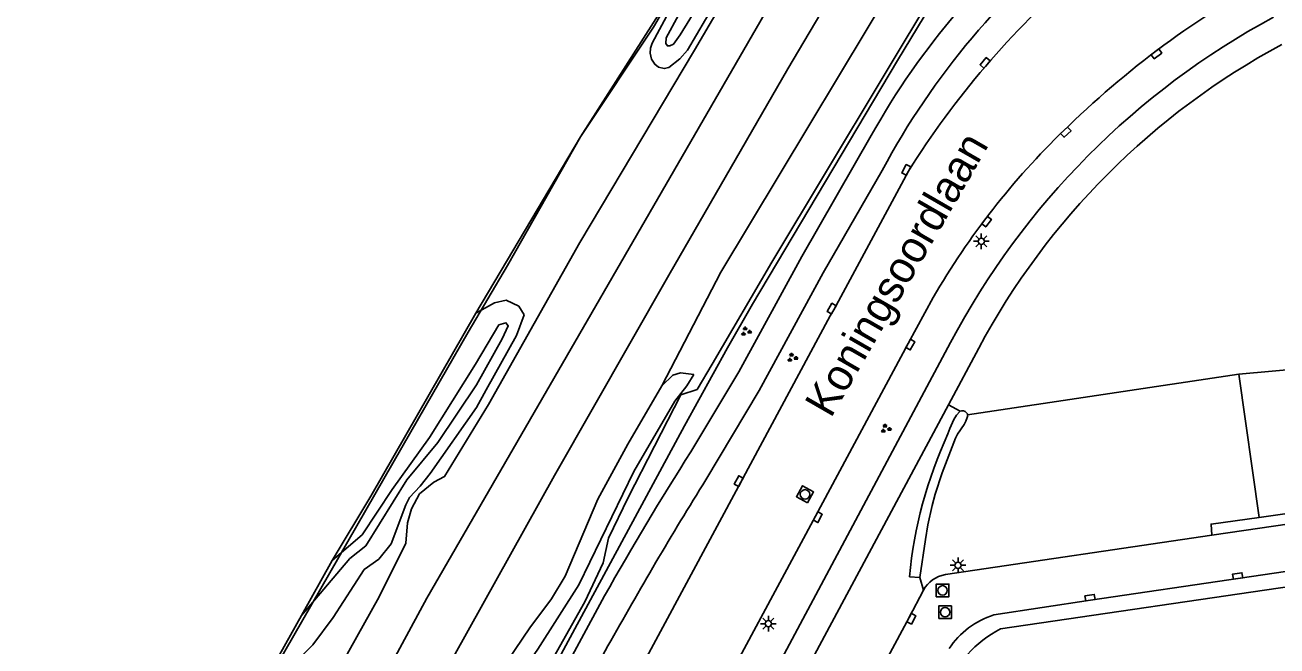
# Model space of a CAD drawing. Extents: x 136000 to 141000, y 400494 to 402006.
# Drawn here: x 137725.4 to 137824.5, y 400640.9 to 400690.1 of the extents above; entities that cross this region are included whole.
import ezdxf

# ---------------------------------------------------------------- set-up
doc = ezdxf.new("R2010")
doc.units = 0
for name, color, linetype in [('gg-afsc-hekwerk', 7, 'Continuous'), ('gg-anno-openbare ruimte label', 7, 'Continuous'), ('gg-aspt-spoorlijn', 7, 'Continuous'), ('gg-knt-BGT kruinlijn', 7, 'Continuous'), ('gg-knt-verharding', 7, 'Continuous'), ('gg-knt-verharding nz', 7, 'Continuous'), ('gt-grn-groengrens', 7, 'Continuous'), ('gt-grn-vlakafsluiter', 7, 'Continuous'), ('gt-symb-groenvak', 7, 'Continuous'), ('gt-symb-kolk', 7, 'Continuous'), ('gt-symb-lichtmast', 7, 'Continuous'), ('gt-symb-rioolschacht', 7, 'Continuous'), ('gx-grn-maaiveld', 7, 'Continuous')]:
    doc.layers.add(name, color=color, linetype=linetype)

# ---------------------------------------------------------------- blocks, each defined once
blk = doc.blocks.new('gt0-KOLK')
at = {"layer": 'gt-symb-kolk'}
blk.add_lwpolyline([(0, 0), (0.375, 0), (0.375, 0.4), (-0.375, 0.4), (-0.375, 0), (0, 0)], dxfattribs=at)
blk = doc.blocks.new('gt0-GRVAK')
at = {"layer": 'gt-symb-groenvak'}
for p, q in [((-0.11, 0.189), (-0.228, 0.24)), ((-0.182, 0.153), (0.088, 0.153)), ((-0.091, 0.211), (-0.156, 0.322)), ((-0.047, 0.214), (-0.047, 0.393)), ((-0.004, 0.211), (0.061, 0.322)), ((0.015, 0.189), (0.133, 0.24)), ((0.262, -0.052), (0.197, 0.059)), ((0.305, -0.049), (0.305, 0.13)), ((0.349, -0.052), (0.414, 0.059)), ((-0.245, -0.228), (-0.363, -0.177)), ((-0.318, -0.264), (-0.047, -0.264)), ((-0.226, -0.206), (-0.291, -0.095)), ((-0.183, -0.203), (-0.183, -0.024)), ((-0.139, -0.206), (-0.074, -0.095)), ((-0.12, -0.228), (-0.002, -0.177)), ((0.243, -0.074), (0.125, -0.023)), ((0.17, -0.11), (0.441, -0.11)), ((0.368, -0.074), (0.486, -0.023))]:
    blk.add_line(p, q, dxfattribs=at)
blk = doc.blocks.new('gt0-LMAST')
at = {"layer": 'gt-symb-lichtmast'}
for p, q in [((-0.182, 0.173), (-0.447, 0.438)), ((-0.005, 0.246), (-0.005, 0.621)), ((0.172, 0.173), (0.437, 0.438)), ((-0.255, -0.004), (-0.63, -0.004)), ((-0.182, -0.181), (-0.447, -0.446)), ((-0.005, -0.254), (-0.005, -0.629)), ((0.437, -0.446), (0.172, -0.181)), ((0.245, -0.004), (0.62, -0.004))]:
    blk.add_line(p, q, dxfattribs=at)
blk.add_circle((-0.005, -0.004), 0.25, dxfattribs=at)
blk = doc.blocks.new('gt0-RS')
at = {"layer": 'gt-symb-rioolschacht'}
blk.add_lwpolyline([(-0.5, -0.5), (0.5, -0.5), (0.5, 0.5), (-0.5, 0.5)], close=True, dxfattribs=at)
blk.add_circle((0, 0), 0.375, dxfattribs=at)

msp = doc.modelspace()

# ---------------------------------------------------------------- linework, layer by layer
at = {"layer": 'gg-afsc-hekwerk'}
for points in [[(137764.981, 400635.036), (137777.587, 400658.382), (137780.977, 400664.557), (137782.964, 400668.027), (137794.433, 400687.317), (137802.189, 400700.171)], [(137673.08, 400500), (137679.073, 400510.921), (137690.13, 400531.89), (137697.24, 400544.984), (137704.068, 400557.915), (137707.189, 400563.436), (137711.427, 400571.311), (137716.123, 400579.98), (137726.152, 400597.957), (137729.988, 400605.237), (137728.496, 400607.87), (137729.573, 400610.191), (137736.665, 400624.377), (137755.903, 400657.896), (137760.436, 400665.803), (137763.569, 400671.08), (137769.351, 400681.269), (137775.737, 400691.291)]]:
    msp.add_lwpolyline(points, dxfattribs=at)
at = {"layer": 'gg-aspt-spoorlijn'}
for points in [[(137684.39, 400500), (137744.114, 400612.492), (137758.139, 400637.988), (137767.293, 400654.443), (137776.333, 400670.325), (137785.754, 400686.663), (137800.006, 400710.764), (137824.915, 400751.953), (137852.49, 400796.886), (137902.562, 400879.015), (137911.759, 400893.922), (138126.55, 401245.58)], [(137679.974, 400500), (137705.761, 400548.658), (137729.975, 400594.291), (137757.164, 400644.72), (137784.911, 400692.764), (137800.887, 400719.606), (137819.846, 400750.938), (138062.157, 401147.541)]]:
    msp.add_lwpolyline(points, dxfattribs=at)
at = {"layer": 'gg-knt-BGT kruinlijn'}
for p, q in [((137761.053, 400667.307), (137762.541, 400668.13)), ((137762.541, 400668.13), (137763.455, 400668.336)), ((137763.455, 400668.336), (137764.472, 400667.851)), ((137752.736, 400652.807), (137761.053, 400667.307)), ((137764.882, 400667.161), (137764.271, 400665.545)), ((137764.472, 400667.851), (137764.882, 400667.161)), ((137764.271, 400665.545), (137761.886, 400661.232)), ((137775.776, 400661.546), (137776.662, 400662.38)), ((137777.258, 400662.587), (137776.662, 400662.38)), ((137778.308, 400662.447), (137777.258, 400662.587)), ((137761.886, 400661.232), (137761.103, 400659.816)), ((137761.103, 400659.816), (137757.43, 400654.587)), ((137757.43, 400654.587), (137756.636, 400653.582)), ((137756.636, 400653.582), (137755.796, 400652.695)), ((137749.695, 400647.703), (137752.736, 400652.807)), ((137755.796, 400652.695), (137755.508, 400652.104)), ((137755.508, 400652.104), (137754.362, 400649.033)), ((137754.362, 400649.033), (137753.379, 400647.808)), ((137753.379, 400647.808), (137752.22, 400646.991)), ((137752.22, 400646.991), (137749.761, 400643.188)), ((137749.761, 400643.188), (137748.139, 400641.005)), ((137748.139, 400641.005), (137745.974, 400638.819))]:
    msp.add_line(p, q, dxfattribs=at)
at = {"layer": 'gg-knt-verharding'}
for p, q in [((137807.982, 400682.131), (137807.627, 400681.801)), ((137798.464, 400660.045), (137800.866, 400664.535)), ((137802.6, 400642.275), (137911.341, 400658.226)), ((137829.009, 400651.137), (137819.324, 400649.706)), ((137819.324, 400649.706), (137798.225, 400646.58))]:
    msp.add_line(p, q, dxfattribs=at)
for points in [[(137792.362, 400681.374), (137786.87, 400671.804), (137781.869, 400662.645), (137778.081, 400656.319)], [(137734.501, 400565.046), (137735.753, 400567.466), (137743.507, 400582.034), (137759.087, 400611.164), (137766.889, 400625.715), (137782.046, 400653.901), (137789.115, 400667.087), (137789.397, 400667.561), (137795.307, 400678.565)], [(137793.23, 400678.613), (137788.563, 400670.492), (137783.49, 400661.185), (137779.265, 400654.107)], [(137797.261, 400668.546), (137795.276, 400664.906), (137787.956, 400651.225), (137780.617, 400637.565), (137775.49, 400627.953)], [(137753.626, 400580.954), (137765.363, 400602.667), (137785.888, 400641.077), (137798.639, 400664.975)], [(137754.898, 400578.717), (137767.638, 400602.418), (137798.464, 400660.045)], [(137796.483, 400645.347), (137795.357, 400643.183), (137793.681, 400640.037)], [(137771.245, 400644.9), (137757.197, 400618.818), (137729.365, 400566.677), (137726.956, 400562.179)], [(137771.514, 400640.926), (137759.873, 400619.176), (137745.495, 400592.359), (137731.641, 400566.467)]]:
    msp.add_lwpolyline(points, dxfattribs=at)
for centre, radius, start, end in [((137842.746, 400653.567), 57.547, 127.20922, 151.10568), ((137846.253, 400650.403), 60.061, 127.72847, 151.98545), ((137854.313, 400641.645), 69.604, 131.00811, 147.96612), ((137857.956, 400630.972), 71.517, 117.42687, 134.32848), ((137853.831, 400635.813), 62.423, 118.34206, 152.14901), ((137852.779, 400636.755), 58.879, 118.3118, 151.848), ((137850.318, 400637.734), 61.355, 134.09129, 149.85473), ((137988.254, 400522.743), 249.029, 147.56189, 150.6243), ((138060.027, 400480.137), 330.292, 148.21624, 150.86901), ((137798.6, 400644.204), 2.406, 98.95746, 151.62481), ((137806.446, 400634.571), 8.611, 116.53057, 160.80357)]:
    msp.add_arc(centre, radius, start, end, dxfattribs=at)
at = {"layer": 'gg-knt-verharding nz'}
msp.add_lwpolyline([(137802.057, 400643.39), (137809.708, 400644.559), (137833.426, 400648.056), (137845.19, 400649.778), (137869.066, 400653.303), (137880.824, 400655.027), (137892.688, 400656.785), (137904.488, 400658.513), (137916.514, 400660.286), (137927.955, 400661.987), (137936.149, 400663.188)], dxfattribs=at)
msp.add_arc((137804.026, 400637.122), 6.57, 107.43748, 146.83527, dxfattribs=at)
at = {"layer": 'gt-grn-groengrens'}
for p, q in [((137855.768, 400665.443), (137821.464, 400662.481)), ((137799.991, 400659.255), (137821.464, 400662.481)), ((137821.464, 400662.481), (137823.059, 400651.118)), ((137799.409, 400659.539), (137798.464, 400660.045)), ((137796.205, 400646.351), (137795.382, 400646.417)), ((137796.205, 400646.351), (137796.483, 400645.347))]:
    msp.add_line(p, q, dxfattribs=at)
for points in [[(137799.991, 400659.255), (137799.999, 400659.197), (137799.965, 400659.032), (137799.856, 400658.735), (137799.706, 400658.47), (137799.18, 400657.702), (137799.034, 400657.4), (137797.97, 400654.637), (137797.428, 400652.971), (137797.18, 400652.067), (137796.852, 400650.527), (137796.649, 400649.362), (137796.205, 400646.351)], [(137798.427, 400657.728), (137798.586, 400658.176), (137798.909, 400658.879), (137799.121, 400659.223), (137799.36, 400659.504), (137799.409, 400659.539)], [(137799.409, 400659.539), (137799.53, 400659.568), (137799.666, 400659.552), (137799.799, 400659.499), (137799.91, 400659.417), (137799.983, 400659.313), (137799.991, 400659.255)], [(137829.009, 400651.137), (137828.964, 400651.947), (137823.059, 400651.118)], [(137823.059, 400651.118), (137819.26, 400650.585), (137819.324, 400649.706)]]:
    msp.add_lwpolyline(points, dxfattribs=at)
msp.add_arc((137829.897, 400643.191), 34.665, 155.20579, 174.65978, dxfattribs=at)
at = {"layer": 'gt-grn-vlakafsluiter'}
msp.add_lwpolyline([(137779.764, 400663.268), (137778.575, 400661.241), (137777.291, 400660.844), (137773.111, 400652.701), (137771.565, 400649.465), (137771.123, 400647.517), (137769.677, 400644.426), (137756.197, 400620.431)], dxfattribs=at)
at = {"layer": 'gx-grn-maaiveld'}
for q in [(137749.695, 400647.703), (137740.602, 400631.425)]:
    msp.add_line((137747.261, 400643.346), q, dxfattribs=at)
for points in [[(137761.053, 400667.307), (137769.351, 400681.269), (137775.129, 400689.98), (137782.948, 400703.379), (137791.888, 400717.898), (137819.729, 400762.646), (137827.31, 400774.613), (137838.632, 400793.323), (137851.402, 400814.902), (137860.72, 400829.797), (137874.341, 400852.974)], [(137786.592, 400702.605), (137779.232, 400690.587), (137777.803, 400688.137), (137777.208, 400687.459), (137776.338, 400686.78), (137775.966, 400686.694), (137775.52, 400686.807), (137775.215, 400687.033), (137774.966, 400687.433), (137774.854, 400687.907), (137774.877, 400688.295), (137775.022, 400688.714), (137776.363, 400691.225), (137788.786, 400711.705), (137800.436, 400730.589), (137803.198, 400734.724), (137803.98, 400735.289), (137804.339, 400735.317), (137804.729, 400735.172), (137805.179, 400734.621), (137805.271, 400734.311), (137805.251, 400734.064), (137803.811, 400731.303)], [(137776.13, 400689.131), (137777.099, 400690.935), (137786.181, 400705.937), (137788.193, 400709.489), (137803.475, 400733.909), (137803.679, 400733.991), (137803.835, 400733.955), (137804.009, 400733.75), (137804.057, 400733.535), (137793.229, 400715.792), (137791.618, 400713.359), (137790.644, 400711.677), (137788.462, 400709.145), (137787.523, 400707.152), (137787.18, 400705.943), (137786.457, 400704.369), (137777.238, 400689.352), (137776.697, 400688.623), (137776.412, 400688.489), (137776.229, 400688.489), (137776.096, 400688.683), (137776.13, 400689.131)], [(137803.593, 400703.113), (137797.549, 400693.154), (137784.5, 400671.342), (137779.764, 400663.268)], [(137697.031, 400539.612), (137715.626, 400574.263), (137724.265, 400590.023), (137725.219, 400592.751), (137725.426, 400593.935), (137726.16, 400595.361), (137727.207, 400596.72), (137730.846, 400603.369), (137745.057, 400629.877), (137753.409, 400644.818), (137755.503, 400649.079), (137755.643, 400650.698), (137755.975, 400651.79), (137756.586, 400652.983), (137757.73, 400653.917), (137758.586, 400654.357), (137762.054, 400660.077), (137769.301, 400672.895), (137778.369, 400688.152), (137785.94, 400701.1)], [(137775.776, 400661.546), (137780.446, 400670.566), (137796.726, 400697.681)], [(137747.261, 400643.346), (137751.086, 400647.864), (137752.345, 400648.857), (137755.593, 400654.104), (137758.05, 400657.062), (137761.102, 400661.615), (137763.146, 400665.257), (137763.622, 400666.307), (137763.442, 400666.541), (137762.879, 400666.369), (137761.037, 400663.274), (137757.384, 400657.455), (137754.442, 400653.337), (137752.05, 400649.73), (137749.695, 400647.703)], [(137725.661, 400566.755), (137730.487, 400575.826), (137734.525, 400582.991), (137735.311, 400584.065), (137736.926, 400585.819), (137737.997, 400587.568), (137739.013, 400589.826), (137739.568, 400591.509), (137741.357, 400595.868), (137743.431, 400599.852), (137746.793, 400605.974), (137749.634, 400610.888), (137751.214, 400613.217), (137751.69, 400614.619), (137753.442, 400618.165), (137756.052, 400622.915), (137759.333, 400629.555), (137763.07, 400636.485), (137765.962, 400640.661), (137769.204, 400645.768), (137773.561, 400654.746), (137776.8, 400660.337), (137777.751, 400661.537), (137778.308, 400662.447)], [(137762.968, 400638.85), (137765.341, 400642.363), (137767.051, 400644.668), (137768.122, 400646.466), (137770.72, 400652.56), (137773.079, 400656.931), (137775.776, 400661.546)]]:
    msp.add_lwpolyline(points, dxfattribs=at)

# ---------------------------------------------------------------- block references
at = {"layer": 'gt-symb-groenvak'}
for p in [(137782.428, 400665.852), (137786.098, 400663.779), (137793.497, 400658.151)]:
    msp.add_blockref('gt0-GRVAK', p, dxfattribs=at)
at = {"layer": 'gt-symb-kolk'}
for p, rotation in [((137814.821, 400688.016), -142.90574963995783), ((137801.527, 400687.015), 49.323434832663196), ((137807.627, 400681.801), -137.1118036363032), ((137795.307, 400678.565), 61.756630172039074), ((137801.332, 400674.678), -127.01999187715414), ((137789.397, 400667.561), 59.25907541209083), ((137795.276, 400664.906), -118.61174774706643), ((137782.046, 400653.901), 61.71673512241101), ((137787.956, 400651.225), -118.15318516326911), ((137821.396, 400646.285), 8.455351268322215), ((137809.708, 400644.559), 8.455351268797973), ((137795.357, 400643.183), -117.93293012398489)]:
    msp.add_blockref('gt0-KOLK', p, dxfattribs=dict(at, rotation=rotation))
at = {"layer": 'gt-symb-lichtmast'}
for p in [(137801.077, 400673.008), (137799.234, 400647.328), (137784.218, 400642.698)]:
    msp.add_blockref('gt0-LMAST', p, dxfattribs=at)
at = {"layer": 'gt-symb-rioolschacht', "rotation": 60.380240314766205}
msp.add_blockref('gt0-RS', (137787.116, 400652.943), dxfattribs=at)
at = {"layer": 'gt-symb-rioolschacht'}
for p in [(137798.006, 400645.333), (137798.205, 400643.602)]:
    msp.add_blockref('gt0-RS', p, dxfattribs=at)

# ---------------------------------------------------------------- texts
at = {"layer": 'gg-anno-openbare ruimte label'}
msp.add_text('Koningsoordlaan', height=2.5, rotation=60, dxfattribs=at).set_placement((137789.158, 400658.92))

doc.saveas('drawing.dxf')
